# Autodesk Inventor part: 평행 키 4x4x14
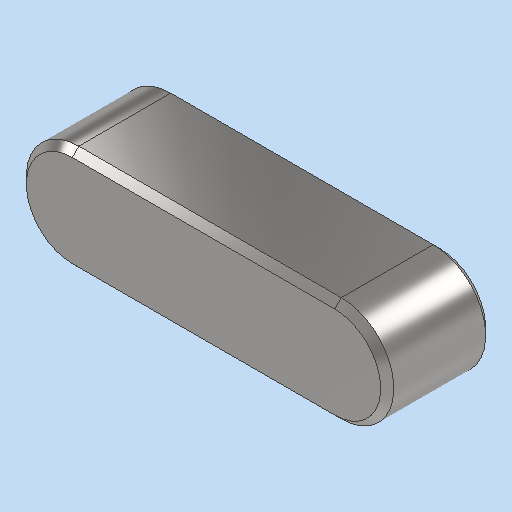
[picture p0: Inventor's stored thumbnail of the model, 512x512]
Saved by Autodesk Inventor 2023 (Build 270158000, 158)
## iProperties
Created: 2024-12
Part Number: 평행 키 4x4x14
Material: 강철, 연강
Description: 키 및 해당 키홈
Document SubType Name: Modeling
Designer: asung
Density: 7.85 g/cm^3
Appearance: 기본값
Author: jhkim
Sending System: Autodesk Inventor 2025
Preprocessor: ST-DEVELOPER v20
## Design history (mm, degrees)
node "평행 키 4x4x141"
node "솔리드1"
body "Solid1"
